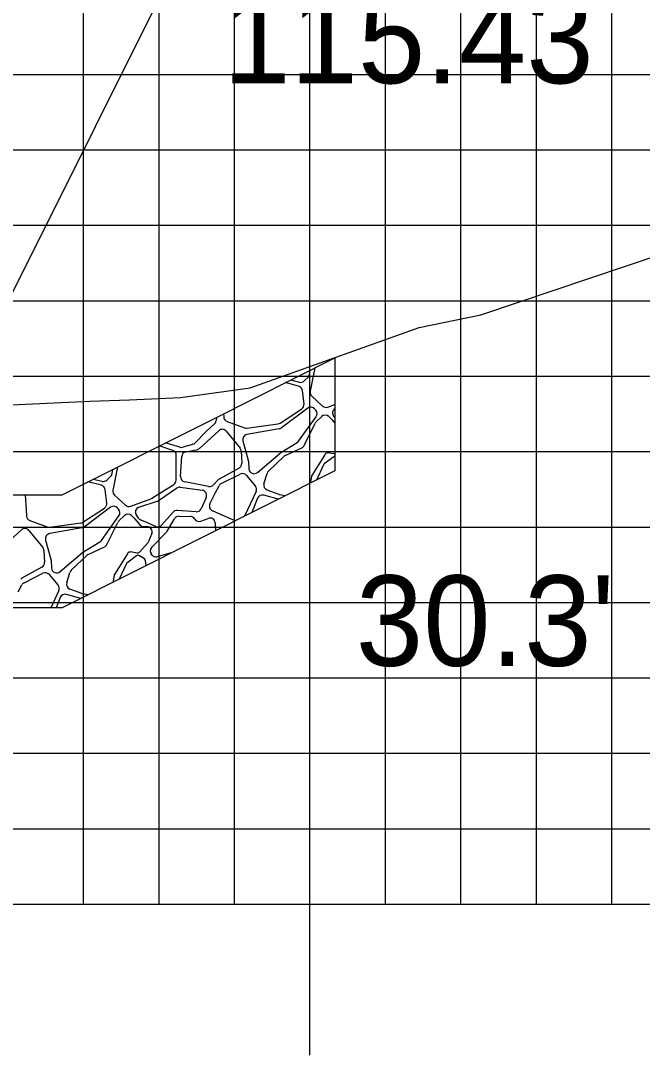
# Model space of a CAD drawing. Extents: x 853328 to 853671, y 364661 to 364881.
# Drawn here: x 853519.46 to 853527.7, y 364684.37 to 364698.09 of the extents above; entities that cross this region are included whole.
import ezdxf

# ---------------------------------------------------------------- set-up
doc = ezdxf.new("R2010")
doc.units = 0
for name, color, linetype in [('ANNOTATION', 7, 'Continuous'), ('D_Roadway_SlopeLines', 7, 'Continuous'), ('D_Text_Standard', 7, 'Continuous'), ('MAJOR', 7, 'Continuous'), ('MINOR', 7, 'Continuous'), ('S_Roadway_Centerline', 7, 'Continuous')]:
    doc.layers.add(name, color=color, linetype=linetype)

msp = doc.modelspace()

# ---------------------------------------------------------------- linework, layer by layer
at = {"layer": 'ANNOTATION'}
for points in [[(853527.358, 364699.13), (853521.666, 364699.13), (853518.012, 364691.803)], [(853523.622, 364693.618), (853523.622, 364692.118), (853520.012, 364690.303)]]:
    msp.add_lwpolyline(points, dxfattribs=at)
at = {"layer": 'D_Roadway_SlopeLines'}
for p, q in [((853523.287, 364693.398), (853523.295, 364693.454)), ((853523.358, 364693.486), (853523.297, 364693.173)), ((853523.144, 364693.241), (853522.966, 364693.289)), ((853523.036, 364693.324), (853523.153, 364693.293)), ((853523.217, 364693.31), (853523.266, 364693.357)), ((853523.215, 364693.005), (853523.194, 364693.183)), ((853523.318, 364693.11), (853523.462, 364692.978)), ((853523.532, 364692.964), (853523.622, 364692.998)), ((853522.148, 364692.877), (853522.151, 364692.833)), ((853522.898, 364692.752), (853523.185, 364692.94)), ((853523.264, 364692.95), (853522.915, 364692.688)), ((853523.371, 364692.923), (853523.355, 364692.941)), ((853522.026, 364692.739), (853521.917, 364692.641)), ((853522.059, 364692.832), (853522.048, 364692.776)), ((853522.196, 364692.772), (853522.427, 364692.69)), ((853522.459, 364692.686), (853522.87, 364692.741)), ((853523.144, 364692.511), (853523.376, 364692.837)), ((853523.217, 364692.455), (853523.363, 364692.75)), ((853523.377, 364692.769), (853523.449, 364692.839)), ((853523.544, 364692.839), (853523.583, 364692.801)), ((853523.589, 364692.795), (853523.622, 364692.752)), ((853523.622, 364692.824), (853523.608, 364692.844)), ((853521.913, 364692.637), (853521.772, 364692.489)), ((853521.829, 364692.415), (853522.085, 364692.651)), ((853522.184, 364692.644), (853522.368, 364692.418)), ((853522.886, 364692.676), (853522.459, 364692.601)), ((853521.476, 364692.39), (853521.297, 364692.449)), ((853521.572, 364692.431), (853521.374, 364692.488)), ((853521.724, 364692.465), (853521.611, 364692.431)), ((853521.743, 364692.471), (853521.724, 364692.465)), ((853522.405, 364692.515), (853522.475, 364692.26)), ((853522.907, 364692.36), (853523.124, 364692.493)), ((853521.521, 364691.996), (853521.523, 364692.325)), ((853521.65, 364692.371), (853521.761, 364692.392)), ((853521.761, 364692.392), (853521.795, 364692.399)), ((853522.383, 364692.378), (853522.391, 364692.219)), ((853522.598, 364692.097), (853522.898, 364692.354)), ((853522.967, 364692.322), (853523.185, 364692.424)), ((853523.494, 364692.341), (853523.317, 364692.058)), ((853523.616, 364692.343), (853523.528, 364692.357)), ((853521.579, 364692.046), (853521.595, 364692.308)), ((853522.478, 364692.247), (853522.485, 364692.144)), ((853522.744, 364692.114), (853522.949, 364692.309)), ((853523.471, 364692.197), (853523.379, 364691.996)), ((853523.609, 364692.306), (853523.481, 364692.21)), ((853520.604, 364691.996), (853520.653, 364692.043)), ((853520.674, 364692.084), (853520.682, 364692.14)), ((853520.745, 364692.172), (853520.684, 364691.859)), ((853522.356, 364692.156), (853522.091, 364692.009)), ((853522.119, 364691.949), (853522.368, 364692.075)), ((853522.451, 364692.058), (853522.569, 364691.919)), ((853522.684, 364691.948), (853522.726, 364692.085)), ((853523.313, 364692.046), (853523.295, 364691.954)), ((853520.531, 364691.927), (853520.353, 364691.975)), ((853520.423, 364692.01), (853520.54, 364691.98)), ((853521.2, 364691.756), (853521.49, 364691.939)), ((853521.575, 364691.901), (853521.867, 364691.861)), ((853521.951, 364691.913), (853521.634, 364691.975)), ((853522.075, 364691.997), (853522.014, 364691.933)), ((853522.043, 364691.83), (853522.089, 364691.92)), ((853519.521, 364691.803), (853519.533, 364691.601)), ((853520.602, 364691.691), (853520.581, 364691.869)), ((853520.705, 364691.796), (853520.849, 364691.664)), ((853521.287, 364691.724), (853521.526, 364691.89)), ((853521.92, 364691.765), (853521.852, 364691.617)), ((853521.968, 364691.682), (853522.043, 364691.83)), ((853522.579, 364691.846), (853522.426, 364691.517)), ((853522.873, 364691.742), (853522.681, 364691.795)), ((853522.885, 364691.805), (853522.726, 364691.864)), ((853522.967, 364691.789), (853522.891, 364691.803)), ((853520.285, 364691.438), (853520.572, 364691.626)), ((853520.651, 364691.636), (853520.302, 364691.374)), ((853520.758, 364691.609), (853520.742, 364691.627)), ((853520.919, 364691.651), (853521.187, 364691.749)), ((853521.028, 364691.636), (853521.269, 364691.715)), ((853522.599, 364691.755), (853522.522, 364691.565)), ((853519.533, 364691.601), (853519.538, 364691.519)), ((853520.531, 364691.197), (853520.763, 364691.524)), ((853520.764, 364691.455), (853520.836, 364691.525)), ((853520.931, 364691.525), (853520.97, 364691.488)), ((853521.028, 364691.486), (853520.995, 364691.53)), ((853521.48, 364691.569), (853521.329, 364691.4)), ((853521.786, 364691.577), (853521.535, 364691.592)), ((853521.559, 364691.517), (853521.709, 364691.514)), ((853521.849, 364691.453), (853521.945, 364691.489)), ((853522.211, 364691.496), (853522.001, 364691.589)), ((853522.303, 364691.455), (853522.211, 364691.496)), ((853519.583, 364691.459), (853519.814, 364691.376)), ((853519.846, 364691.373), (853520.257, 364691.428)), ((853520.273, 364691.362), (853519.846, 364691.287)), ((853520.604, 364691.142), (853520.75, 364691.436)), ((853520.976, 364691.481), (853521.034, 364691.407)), ((853521.251, 364691.382), (853521.056, 364691.464)), ((853521.087, 364691.381), (853521.136, 364691.38)), ((853521.402, 364691.32), (853521.498, 364691.483)), ((853521.765, 364691.483), (853521.768, 364691.479)), ((853522.037, 364691.429), (853522.043, 364691.324)), ((853519.216, 364691.102), (853519.472, 364691.337)), ((853519.571, 364691.33), (853519.755, 364691.104)), ((853521.198, 364691.287), (853521.157, 364691.18)), ((853521.196, 364691.103), (853521.392, 364691.307)), ((853519.792, 364691.201), (853519.862, 364690.946)), ((853520.294, 364691.046), (853520.511, 364691.179)), ((853520.354, 364691.008), (853520.572, 364691.11)), ((853521.15, 364691.169), (853521.034, 364691.04)), ((853519.77, 364691.064), (853519.778, 364690.906)), ((853519.985, 364690.783), (853520.285, 364691.04)), ((853520.131, 364690.8), (853520.336, 364690.995)), ((853520.881, 364691.027), (853520.704, 364690.744)), ((853520.996, 364690.992), (853520.868, 364690.896)), ((853521.003, 364691.029), (853520.915, 364691.043)), ((853521.101, 364690.951), (853521.035, 364690.993)), ((853521.2, 364691.003), (853521.192, 364691.012)), ((853521.438, 364691.026), (853521.27, 364690.981)), ((853519.743, 364690.843), (853519.478, 364690.695)), ((853519.865, 364690.933), (853519.872, 364690.83)), ((853520.858, 364690.883), (853520.766, 364690.682)), ((853521.123, 364690.862), (853521.116, 364690.926)), ((853519.506, 364690.636), (853519.755, 364690.761)), ((853519.838, 364690.745), (853519.956, 364690.606)), ((853520.071, 364690.635), (853520.113, 364690.771)), ((853520.7, 364690.732), (853520.682, 364690.64)), ((853519.43, 364690.516), (853519.476, 364690.606)), ((853519.966, 364690.533), (853519.859, 364690.303)), ((853520.272, 364690.491), (853520.113, 364690.551)), ((853519.986, 364690.441), (853519.93, 364690.303)), ((853520.26, 364690.428), (853520.068, 364690.481)), ((853520.354, 364690.475), (853520.278, 364690.489))]:
    msp.add_line(p, q, dxfattribs=at)
for points in [[(853520.012, 364690.303), (853518.012, 364690.303), (853510.296, 364694.161)], [(853518.012, 364691.803), (853520.012, 364691.803), (853522.012, 364692.803), (853523.623, 364693.619)], [(853518.012, 364691.803), (853520.012, 364691.803)]]:
    msp.add_lwpolyline(points, dxfattribs=at)
for centre, radius, start, end in [((853523.17, 364693.36), 0.0684, 255.5862, 313.5509), ((853523.219, 364693.407), 0.0684, 313.5509, 352.4768), ((853523.126, 364693.175), 0.0684, 6.772, 74.9337), ((853523.364, 364693.16), 0.0684, 168.9168, 227.617), ((853523.147, 364692.997), 0.0684, 303.217, 6.772), ((853523.305, 364692.895), 0.0684, 42.2166, 126.8468), ((853523.321, 364692.877), 0.0684, 324.494, 42.2166), ((853523.508, 364693.029), 0.0684, 227.617, 290.2094), ((853523.662, 364692.885), 0.0684, 125.893, 216.9973), ((853521.981, 364692.79), 0.0684, 311.9476, 348.6455), ((853522.219, 364692.837), 0.0684, 183.3369, 250.2657), ((853522.861, 364692.809), 0.0684, 277.6287, 303.217), ((853523.424, 364692.72), 0.0684, 133.974, 153.6813), ((853523.496, 364692.789), 0.0684, 46.2291, 133.974), ((853523.535, 364692.752), 0.0684, 38.3261, 46.2291), ((853521.963, 364692.59), 0.0684, 131.9476, 136.3463), ((853522.131, 364692.601), 0.0684, 39.0999, 132.6379), ((853522.471, 364692.533), 0.0684, 99.9595, 195.3992), ((853522.45, 364692.754), 0.0684, 250.2657, 277.6287), ((853522.874, 364692.743), 0.0684, 279.9595, 306.8468), ((853521.723, 364692.537), 0.0684, 286.8267, 316.3463), ((853523.088, 364692.551), 0.0684, 301.4561, 324.494), ((853523.156, 364692.486), 0.0684, 295.1231, 333.6813), ((853521.455, 364692.325), 0.0684, 359.6616, 71.6925), ((853521.591, 364692.497), 0.0684, 253.8136, 286.8267), ((853521.663, 364692.304), 0.0684, 100.7471, 176.519), ((853521.782, 364692.466), 0.0684, 280.7471, 312.6379), ((853522.315, 364692.374), 0.0684, 2.73, 39.0999), ((853522.943, 364692.302), 0.0684, 121.4561, 130.552), ((853522.996, 364692.26), 0.0684, 115.1231, 133.5911), ((853523.523, 364692.323), 0.0342, 81.1548, 148.0655), ((853523.629, 364692.278), 0.0342, 101.7007, 126.8965), ((853523.621, 364692.377), 0.0342, 261.1548, 271.4679), ((853522.322, 364692.216), 0.0684, 299.1291, 2.73), ((853522.41, 364692.242), 0.0684, 4.17, 15.3992), ((853523.502, 364692.183), 0.0342, 126.8965, 155.4667), ((853520.606, 364692.093), 0.0684, 313.5509, 352.4768), ((853521.647, 364692.042), 0.0684, 176.519, 258.9983), ((853522.399, 364692.014), 0.0684, 40.2744, 116.7813), ((853522.553, 364692.149), 0.0684, 184.17, 310.552), ((853522.791, 364692.065), 0.0684, 133.5911, 163.0564), ((853523.346, 364692.04), 0.0342, 148.0655, 169.2871), ((853520.513, 364691.861), 0.0684, 6.772, 74.9337), ((853520.557, 364692.046), 0.0684, 255.5862, 313.5509), ((853521.453, 364691.997), 0.0684, 302.2918, 359.6616), ((853521.565, 364691.833), 0.0684, 82.13, 124.636), ((853521.964, 364691.98), 0.0684, 258.9983, 299.3713), ((853521.964, 364691.98), 0.0684, 299.3713, 316.1325), ((853522.124, 364691.949), 0.0684, 119.1291, 136.1325), ((853522.15, 364691.888), 0.0684, 116.7813, 152.9117), ((853522.517, 364691.875), 0.0684, 335.0655, 40.2744), ((853522.75, 364691.929), 0.0684, 163.0564, 249.4816), ((853520.751, 364691.846), 0.0684, 168.9168, 227.617), ((853521.857, 364691.793), 0.0684, 335.577, 82.13), ((853522.662, 364691.729), 0.0684, 74.5701, 157.9387), ((853522.897, 364691.837), 0.0342, 249.4816, 259.2871), ((853520.534, 364691.683), 0.0684, 303.217, 6.772), ((853520.692, 364691.581), 0.0684, 42.2166, 126.8468), ((853520.895, 364691.715), 0.0684, 227.617, 290.2094), ((853521.049, 364691.571), 0.0684, 108.2213, 216.9973), ((853521.163, 364691.814), 0.0684, 290.2094, 302.2918), ((853521.248, 364691.78), 0.0684, 288.2213, 304.636), ((853522.029, 364691.651), 0.0684, 152.9117, 246.1637), ((853519.606, 364691.523), 0.0684, 183.3369, 250.2657), ((853520.708, 364691.563), 0.0684, 324.494, 42.2166), ((853520.883, 364691.476), 0.0684, 46.2291, 133.974), ((853521.531, 364691.524), 0.0684, 86.6239, 138.2335), ((853521.557, 364691.449), 0.0684, 88.8449, 149.373), ((853521.708, 364691.446), 0.0684, 33.5353, 88.8449), ((853521.79, 364691.645), 0.0684, 266.6239, 335.577), ((853521.969, 364691.425), 0.0684, 3.0104, 110.6383), ((853519.518, 364691.287), 0.0684, 39.0999, 132.6379), ((853519.837, 364691.44), 0.0684, 250.2657, 277.6287), ((853520.248, 364691.495), 0.0684, 277.6287, 303.217), ((853520.261, 364691.429), 0.0684, 279.9595, 306.8468), ((853520.811, 364691.406), 0.0684, 133.974, 153.6813), ((853520.922, 364691.438), 0.0684, 38.3261, 46.2291), ((853521.082, 364691.527), 0.0684, 216.9973, 247.2938), ((853521.088, 364691.449), 0.0684, 218.3261, 269.0465), ((853521.134, 364691.312), 0.0684, 338.8998, 89.0465), ((853521.278, 364691.445), 0.0684, 247.2938, 318.2335), ((853521.825, 364691.517), 0.0684, 213.5353, 290.6383), ((853519.858, 364691.22), 0.0684, 99.9595, 195.3992), ((853521.343, 364691.355), 0.0684, 316.0985, 329.373), ((853519.702, 364691.061), 0.0684, 2.73, 39.0999), ((853520.475, 364691.237), 0.0684, 301.4561, 324.494), ((853520.543, 364691.172), 0.0684, 295.1231, 333.6813), ((853521.125, 364691.192), 0.0342, 317.8866, 338.8998), ((853521.245, 364691.056), 0.0684, 136.0985, 219.8265), ((853519.797, 364690.928), 0.0684, 4.17, 15.3992), ((853520.33, 364690.988), 0.0684, 121.4561, 130.552), ((853520.383, 364690.946), 0.0684, 115.1231, 133.5911), ((853520.91, 364691.009), 0.0342, 81.1548, 148.0655), ((853521.016, 364690.965), 0.0342, 57.3432, 126.8965), ((853521.008, 364691.063), 0.0342, 261.1548, 317.8866), ((853521.082, 364690.922), 0.0342, 5.6996, 57.3432), ((853521.252, 364691.047), 0.0684, 219.8265, 285.0589), ((853521.456, 364690.96), 0.0684, 91.1328, 105.0589), ((853519.709, 364690.902), 0.0684, 299.1291, 2.73), ((853519.94, 364690.835), 0.0684, 184.17, 310.552), ((853520.889, 364690.869), 0.0342, 126.8965, 155.4667), ((853519.511, 364690.635), 0.0684, 119.1291, 136.1325), ((853519.786, 364690.7), 0.0684, 40.2744, 116.7813), ((853520.178, 364690.751), 0.0684, 133.5911, 163.0564), ((853520.733, 364690.726), 0.0342, 148.0655, 169.2871), ((853519.537, 364690.575), 0.0684, 116.7813, 152.9117), ((853519.904, 364690.561), 0.0684, 335.0655, 40.2744), ((853520.137, 364690.615), 0.0684, 163.0564, 249.4816), ((853520.049, 364690.415), 0.0684, 74.5701, 157.9387), ((853520.284, 364690.523), 0.0342, 249.4816, 259.2871)]:
    msp.add_arc(centre, radius, start, end, dxfattribs=at)
at = {"layer": 'MAJOR'}
for p, q in [((853523.294, 364686.374), (853523.294, 364721.374)), ((853353.294, 364696.374), (853633.294, 364696.374)), ((853353.294, 364691.374), (853633.294, 364691.374)), ((853353.294, 364686.374), (853633.294, 364686.374)), ((853353.294, 364686.374), (853633.294, 364686.374)), ((853523.294, 364684.37), (853523.294, 364686.374))]:
    msp.add_line(p, q, dxfattribs=at)
at = {"layer": 'MINOR'}
for p, q in [((853520.294, 364686.374), (853520.294, 364721.374)), ((853521.294, 364686.374), (853521.294, 364721.374)), ((853522.294, 364686.374), (853522.294, 364721.374)), ((853524.294, 364686.374), (853524.294, 364721.374)), ((853525.294, 364686.374), (853525.294, 364721.374)), ((853526.294, 364686.374), (853526.294, 364721.374)), ((853527.294, 364686.374), (853527.294, 364721.374)), ((853353.294, 364697.374), (853633.294, 364697.374)), ((853353.294, 364695.374), (853633.294, 364695.374)), ((853353.294, 364694.374), (853633.294, 364694.374)), ((853353.294, 364693.374), (853633.294, 364693.374)), ((853353.294, 364692.374), (853633.294, 364692.374)), ((853353.294, 364690.374), (853633.294, 364690.374)), ((853353.294, 364689.374), (853633.294, 364689.374)), ((853353.294, 364688.374), (853633.294, 364688.374)), ((853353.294, 364687.374), (853633.294, 364687.374))]:
    msp.add_line(p, q, dxfattribs=at)
at = {"layer": 'S_Roadway_Centerline'}
msp.add_lwpolyline([(853504.411, 364697.662), (853514.458, 364692.889), (853514.544, 364692.865), (853514.553, 364692.864), (853515.183, 364692.857), (853516.136, 364692.862), (853516.267, 364692.854), (853517.81, 364692.927), (853518.388, 364692.95), (853520.377, 364693.042), (853520.905, 364693.06), (853521.578, 364693.091), (853522.503, 364693.219), (853524.741, 364694.018), (853525.558, 364694.185), (853531.833, 364696.3), (853538.039, 364698.785), (853544.252, 364701.555)], dxfattribs=at)

# ---------------------------------------------------------------- texts
at = {"layer": 'ANNOTATION'}
msp.add_text('115.43', height=1.2, dxfattribs=at).set_placement((853522.144, 364697.257))
at = {"layer": 'D_Text_Standard'}
msp.add_text("30.3'", height=1.2, dxfattribs=at).set_placement((853523.901, 364689.533))

doc.saveas('drawing.dxf')
